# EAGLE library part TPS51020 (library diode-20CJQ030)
TI's TPS51020 dual voltage mode, DDR selectable, synchronous, step-down controller for notebook system power Description: The TPS51020 is a multi-function dualsynchronousstep-down controller for notebook system power. The part is specifically designed for high performance, high efficiency applications where the loss associated with a current sense resistor is unacceptable. The TPS51020 utilizes feed forward voltage mode control to attain high efficiency without sacrificing line response. Efficiency at light load conditions can be maintained high as well by incorporating autoskip operation. A selectable, Suspend to RAM (STR) supported, DDR option provides a one chip solution for all switching applications from 5-V/3.3-V supply to a complete DDR termination solution. Features: Wide Input Voltage Range: 4.5-V to 28-V Selectable Dual and DDR Modes Selectable Fixed Frequency Voltage Mode Integrated Selectable Output Discharge Advanced Power Good Logic Monitors bothChannels Selectable Autoskip Mode Integrated Boot Strap Diodes 180° Phase Shift Between Channels Integrated 5-V, 60-mA Regulator Input Feedforward Control 1% Internal 0.85-V Reference RDS(on) Overcurrent Detection (4200 ppm/°C) Integrated OVP, UVP and Power Good Timers 30-pin TSSOP Package Applications: Notebook Computers System Bus and I/O DDR I or DDR II Termination Please send any comments to: messi@users.sourceforge.net
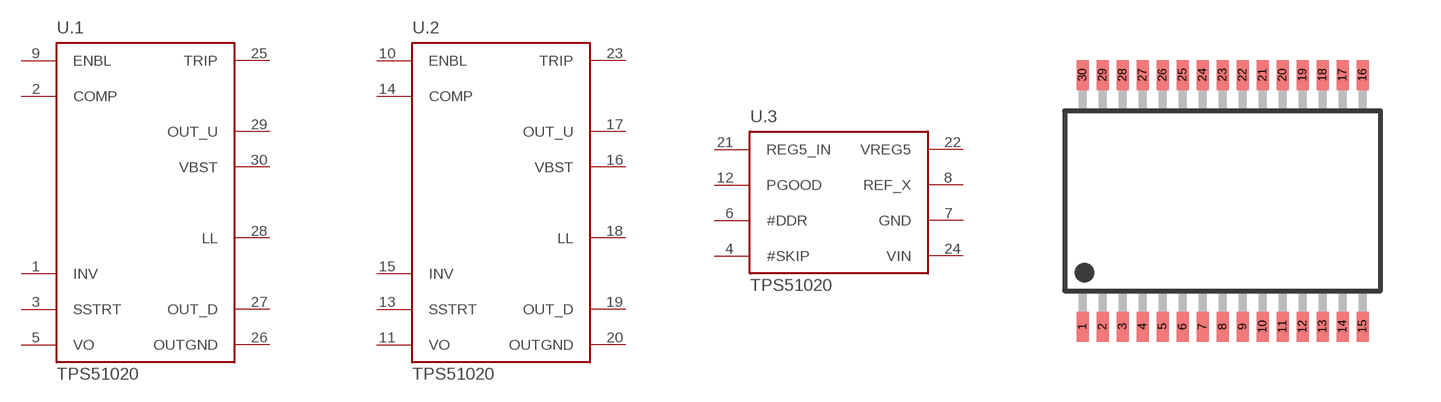
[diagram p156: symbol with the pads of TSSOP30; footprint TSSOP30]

Designator prefix U; gates .1=TPS51020 .2=TPS51020 .3=TPS51020_PWR

## TPS51020  [TSSOP30]
1  .1:INV  in
2  .1:COMP  in
3  .1:SSTRT  in
4  .3:#SKIP  in
5  .1:VO  in
6  .3:#DDR  in
7  .3:GND  pwr
8  .3:REF_X  out
9  .1:ENBL  in
10  .2:ENBL  in
11  .2:VO  in
12  .3:PGOOD  in
13  .2:SSTRT  in
14  .2:COMP  in
15  .2:INV  in
16  .2:VBST  in
17  .2:OUT_U  out
18  .2:LL
19  .2:OUT_D  out
20  .2:OUTGND  out
21  .3:REG5_IN  in
22  .3:VREG5  out
23  .2:TRIP  in
24  .3:VIN  pwr
25  .1:TRIP  in
26  .1:OUTGND  out
27  .1:OUT_D  out
28  .1:LL
29  .1:OUT_U  out
30  .1:VBST  in

## Footprint TSSOP30 (pad centres in mm)
smd 0.3 x 0.75: 1 -3.5,-3.15; 2 -3,-3.15; 3 -2.5,-3.15; 4 -2,-3.15; 5 -1.5,-3.15; 6 -1,-3.15; 7 -0.5,-3.15; 8 0,-3.15; 9 0.5,-3.15; 10 1,-3.15; 11 1.5,-3.15; 12 2,-3.15; 13 2.5,-3.15; 14 3,-3.15; 15 3.5,-3.15; 16 3.5,3.15; 17 3,3.15; 18 2.5,3.15; 19 2,3.15; 20 1.5,3.15; 21 1,3.15; 22 0.5,3.15; 23 0,3.15; 24 -0.5,3.15; 25 -1,3.15; 26 -1.5,3.15; 27 -2,3.15; 28 -2.5,3.15; 29 -3,3.15; 30 -3.5,3.15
